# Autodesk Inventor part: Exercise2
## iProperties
Shininess: 77.0
Length Units: 11269
Angle Units: 11279
Time Units: 11290
Mass Units: 11283
Length Display Precision: 3
Angle Display Precision: 2
Created: 2001-12
Part Number: Exercise2
Document SubType Name: Modeling
Designer: Renu Muthoo
Density: 1 g/cm^3
Density: 0.0
Volumn: 0.0
Area: 0.0
PropertySet Name: Model Information
Control State: 0
Master: False
Checked Out: False
Author: Renu Muthoo
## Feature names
1. Extrusion1
2. Extrusion2
3. Extrusion3
4. Fillet1
5. Mirror1
